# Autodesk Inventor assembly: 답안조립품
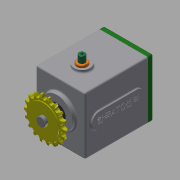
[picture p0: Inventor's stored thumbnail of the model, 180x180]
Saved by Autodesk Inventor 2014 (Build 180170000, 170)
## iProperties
Created: 2018-12
Part Number: 답안조립품
Document SubType Name: Assembly
Designer: kh
Mass: 1856.81 g
Surface Area: 1968.31 cm^2
Volume: 815.223 cm^3
Density: 2.27767 g/cm^3
Author: kh
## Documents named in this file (16)
- C:\Users\kh\Desktop\381207V1031\답안조립품.iam
- C:\Users\kh\Desktop\381207V1031\본체.ipt
- C:\Users\kh\Desktop\381207V1031\가변스프링.ipt
- C:\Users\kh\Desktop\381207V1031\멈춤나사 M3x8.ipt
- C:\Users\kh\Desktop\381207V1031\메인 기어 축.ipt
- C:\Users\kh\Desktop\381207V1031\베어링 608.ipt
- C:\Users\kh\Desktop\381207V1031\베어링 6003.ipt
- C:\Users\kh\Desktop\381207V1031\볼트 M4 x 10.ipt
- C:\Users\kh\Desktop\381207V1031\부시.ipt
- C:\Users\kh\Desktop\381207V1031\서브 기어 축.ipt
- C:\Users\kh\Desktop\381207V1031\스프로킷.ipt
- C:\Users\kh\Desktop\381207V1031\슬라이더.ipt
- C:\Users\kh\Desktop\381207V1031\오일 실 8 22 7.ipt
- C:\Users\kh\Desktop\381207V1031\오일 실 17 32 8.ipt
- C:\Users\kh\Desktop\381207V1031\커버.ipt
- C:\Users\kh\Desktop\381207V1031\키 5 x 5 x 18.ipt
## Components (1 placed, 1 different names)
1. 가변스프링:1 — Mate:29, Mate:30
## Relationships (2: Mate 2)
- Mate:29: 가변스프링:1
- Mate:30: 가변스프링:1
